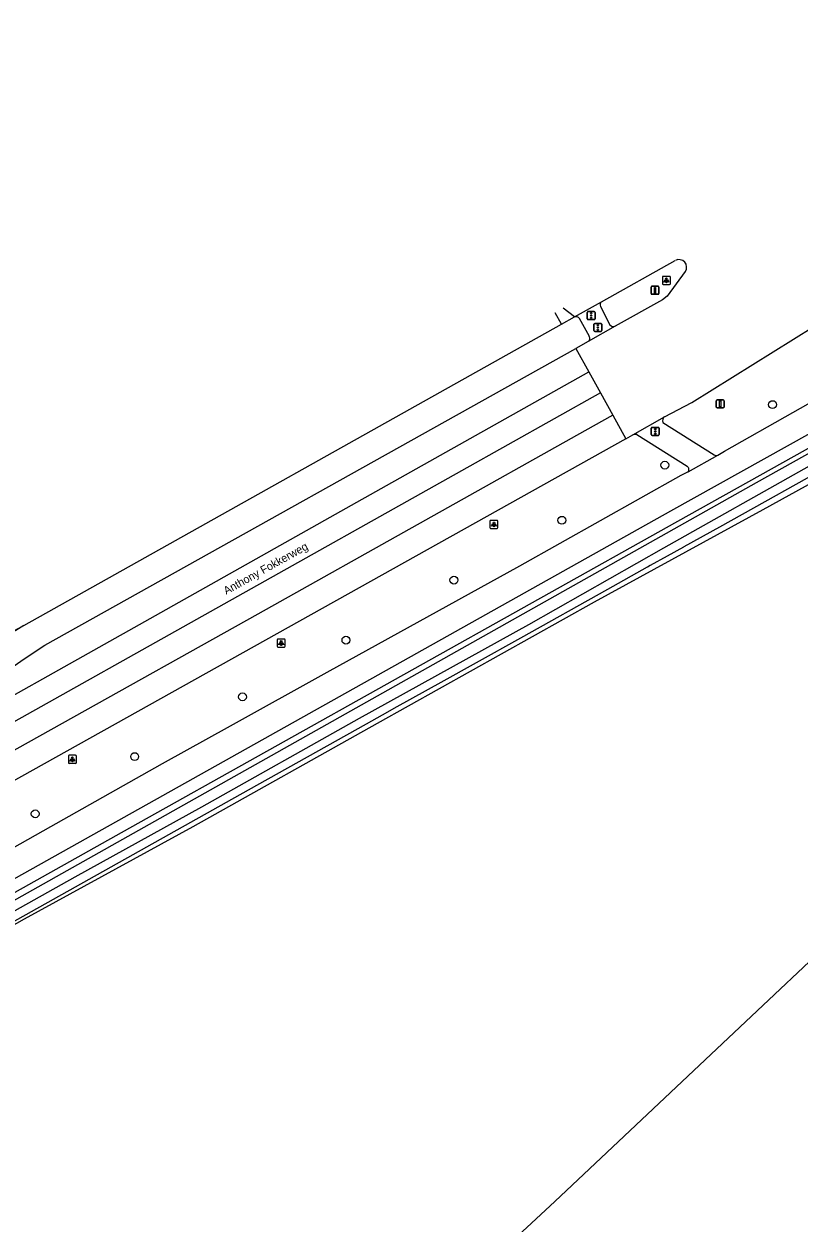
# Model space of a CAD drawing. Extents: x 157154 to 159278, y 385000 to 386650.
# Drawn here: x 157263.6 to 157360.5, y 386097.5 to 386247.3 of the extents above; entities that cross this region are included whole.
import ezdxf

# ---------------------------------------------------------------- set-up
doc = ezdxf.new("R2010")
doc.units = 0
for name, color, linetype in [('IMGEO_Boom', 7, 'Continuous'), ('IMGEO_Bouwland', 7, 'Continuous'), ('IMGEO_Fietspad_gesloten', 7, 'Continuous'), ('IMGEO_Fietspad_open', 7, 'Continuous'), ('IMGEO_Groenvoorziening', 7, 'Continuous'), ('IMGEO_Lichtpunt', 7, 'Continuous'), ('IMGEO_Loofbos', 7, 'Continuous'), ('IMGEO_Openbare_ruimte_label', 7, 'Continuous'), ('IMGEO_Portaal', 7, 'Continuous'), ('IMGEO_Rijbaan_regionaal_gesloten', 7, 'Continuous'), ('IMGEO_Verkeersregelinstallatiepaal', 7, 'Continuous'), ('IMGEO_Voetpad_open', 7, 'Continuous'), ('IMGEO_Waterloop', 7, 'Continuous')]:
    doc.layers.add(name, color=color, linetype=linetype)

msp = doc.modelspace()

# ---------------------------------------------------------------- linework, layer by layer
at = {"layer": 'IMGEO_Boom'}
for centre in [(157357.17, 386199.78), (157343.71, 386192.22), (157330.85, 386185.33), (157317.36, 386177.85), (157303.87, 386170.35), (157290.95, 386163.26), (157277.48, 386155.8), (157265.05, 386148.65)]:
    msp.add_circle(centre, 0.489, dxfattribs=at)
at = {"layer": 'IMGEO_Bouwland'}
msp.add_lwpolyline([(157390.33, 386206.23), (157370.97, 386194.93), (157355.94, 386186.64), (157334.87, 386175.09), (157307.76, 386159.95), (157284.74, 386147.04), (157263.69, 386135.49), (157241.46, 386122.96), (157215.19, 386108.12), (157203.72, 386101.65), (157202.61, 386100.97)], dxfattribs=at)
at = {"layer": 'IMGEO_Fietspad_gesloten'}
for points in [[(157350.32, 386193.47), (157351.18, 386193.97), (157376.79, 386208.46)], [(157379.77, 386206.17), (157344.43, 386186.45), (157276.11, 386148.18), (157237.43, 386126.52), (157197.41, 386104.01), (157185.77, 386096.92)], [(157346.62, 386191.38), (157350.32, 386193.47)], [(157346.62, 386191.38), (157345.73, 386190.93), (157325.57, 386179.6), (157301.5, 386166.32), (157289.42, 386159.61), (157280.92, 386154.89), (157265.99, 386146.48), (157249.02, 386136.91), (157232.77, 386127.85), (157216.57, 386118.79), (157199.15, 386108.93), (157192.54, 386105.06), (157189.59, 386103.18), (157183.83, 386099.48)]]:
    msp.add_lwpolyline(points, dxfattribs=at)
at = {"layer": 'IMGEO_Fietspad_open'}
for points in [[(157335.66, 386212.04), (157336.85, 386209.75)], [(157334.28, 386208.3), (157333.04, 386210.54)], [(157343.48, 386197.56), (157349.86, 386193.5)], [(157340.23, 386196.05), (157346.52, 386192.07)]]:
    msp.add_lwpolyline(points, dxfattribs=at)
for centre, radius, start, end in [((157336.15, 386212.23), 0.525, 133.694, 201.4184), ((157332.63, 386210.28), 0.484, 32.5209, 113.9937), ((157337.28, 386210.07), 0.535, 217.4867, 294.815), ((157333.86, 386208.07), 0.477, 303.1806, 29.0462), ((157344.03, 386197.79), 0.598, 129.3964, 202.7643), ((157340.1, 386195.09), 0.974, 82.0163, 112.7027), ((157350.12, 386193.89), 0.469, 236.3585, 295.7342), ((157346.25, 386191.68), 0.47, 321.1296, 55.9729)]:
    msp.add_arc(centre, radius, start, end, dxfattribs=at)
at = {"layer": 'IMGEO_Groenvoorziening'}
msp.add_lwpolyline([(157436.28, 386247.34), (157433.75, 386245.51), (157419, 386234.87), (157403.65, 386220.37), (157399.91, 386217.07), (157393.88, 386212.34), (157382.1, 386205.07), (157355.13, 386190.01), (157200.73, 386103.12)], dxfattribs=at)
at = {"layer": 'IMGEO_Lichtpunt'}
for p, q in [((157343.41, 386215.7), (157343.41, 386214.89)), ((157343.41, 386215.7), (157343.41, 386214.89)), ((157344.31, 386215.79), (157343.5, 386215.79)), ((157344.31, 386215.79), (157343.5, 386215.79)), ((157344.41, 386214.89), (157344.41, 386215.7)), ((157344.41, 386214.89), (157344.41, 386215.7)), ((157343.5, 386214.8), (157344.31, 386214.8)), ((157343.5, 386214.8), (157344.31, 386214.8)), ((157321.86, 386185.22), (157321.86, 386184.41)), ((157321.86, 386185.22), (157321.86, 386184.41)), ((157322.76, 386185.31), (157321.95, 386185.31)), ((157322.76, 386185.31), (157321.95, 386185.31)), ((157321.95, 386184.31), (157322.76, 386184.31)), ((157321.95, 386184.31), (157322.76, 386184.31)), ((157322.86, 386184.41), (157322.86, 386185.22)), ((157322.86, 386184.41), (157322.86, 386185.22)), ((157295.28, 386170.39), (157295.28, 386169.59)), ((157295.28, 386170.39), (157295.28, 386169.59)), ((157296.18, 386170.49), (157295.37, 386170.49)), ((157296.18, 386170.49), (157295.37, 386170.49)), ((157295.37, 386169.49), (157296.18, 386169.49)), ((157295.37, 386169.49), (157296.18, 386169.49)), ((157296.28, 386169.59), (157296.28, 386170.39)), ((157296.28, 386169.59), (157296.28, 386170.39)), ((157269.2, 386155.86), (157269.2, 386155.05)), ((157269.2, 386155.86), (157269.2, 386155.05)), ((157270.1, 386155.96), (157269.29, 386155.96)), ((157270.1, 386155.96), (157269.29, 386155.96)), ((157270.19, 386155.05), (157270.19, 386155.86)), ((157270.19, 386155.05), (157270.19, 386155.86)), ((157269.29, 386154.96), (157270.1, 386154.96)), ((157269.29, 386154.96), (157270.1, 386154.96))]:
    msp.add_line(p, q, dxfattribs=at)
for points in [[(157343.78, 386215.36), (157343.82, 386215.33), (157343.64, 386215.07), (157343.6, 386215.1), (157343.78, 386215.36)], [(157343.89, 386215.31), (157343.93, 386215.31), (157343.93, 386214.99), (157343.89, 386214.99), (157343.89, 386215.31)], [(157344, 386215.33), (157344.03, 386215.36), (157344.22, 386215.1), (157344.18, 386215.07), (157344, 386215.33)], [(157322.23, 386184.88), (157322.27, 386184.85), (157322.09, 386184.59), (157322.05, 386184.62), (157322.23, 386184.88)], [(157322.34, 386184.83), (157322.38, 386184.83), (157322.38, 386184.51), (157322.34, 386184.51), (157322.34, 386184.83)], [(157322.45, 386184.85), (157322.48, 386184.88), (157322.67, 386184.62), (157322.63, 386184.59), (157322.45, 386184.85)], [(157295.65, 386170.06), (157295.69, 386170.03), (157295.5, 386169.77), (157295.47, 386169.8), (157295.65, 386170.06)], [(157295.75, 386170.01), (157295.8, 386170.01), (157295.8, 386169.69), (157295.75, 386169.69), (157295.75, 386170.01)], [(157295.86, 386170.03), (157295.9, 386170.06), (157296.09, 386169.79), (157296.05, 386169.77), (157295.86, 386170.03)], [(157269.57, 386155.52), (157269.61, 386155.5), (157269.42, 386155.23), (157269.38, 386155.26), (157269.57, 386155.52)], [(157269.67, 386155.48), (157269.72, 386155.48), (157269.72, 386155.15), (157269.67, 386155.15), (157269.67, 386155.48)], [(157269.78, 386155.5), (157269.82, 386155.52), (157270.01, 386155.26), (157269.97, 386155.23), (157269.78, 386155.5)]]:
    msp.add_lwpolyline(points, dxfattribs=at)
for centre in [(157343.91, 386215.5), (157322.36, 386185.01), (157295.78, 386170.19), (157269.7, 386155.66)]:
    msp.add_circle(centre, 0.0994, dxfattribs=at)
for centre, start, end in [((157343.5, 386215.7), 90, 180), ((157343.5, 386215.7), 90, 180), ((157344.31, 386215.7), 0, 90), ((157344.31, 386215.7), 0, 90), ((157343.5, 386214.89), 180, 270), ((157343.5, 386214.89), 180, 270), ((157344.31, 386214.89), 270, 0), ((157344.31, 386214.89), 270, 360), ((157321.95, 386185.22), 90, 180), ((157321.95, 386185.22), 90, 180), ((157321.95, 386184.41), 180, 270), ((157321.95, 386184.41), 180, 270), ((157322.76, 386185.22), 0, 90), ((157322.76, 386185.22), 0, 90), ((157322.76, 386184.41), 270, 0), ((157322.76, 386184.41), 270, 360), ((157295.37, 386170.39), 90, 180), ((157295.37, 386170.39), 90, 180), ((157295.37, 386169.59), 180, 270), ((157295.37, 386169.59), 180, 270), ((157296.18, 386170.39), 0, 90), ((157296.18, 386170.39), 0, 90), ((157296.18, 386169.59), 270, 0), ((157296.18, 386169.59), 270, 360), ((157269.29, 386155.86), 90, 180), ((157269.29, 386155.86), 90, 180), ((157270.1, 386155.86), 0, 90), ((157270.1, 386155.86), 0, 90), ((157269.29, 386155.05), 180, 270), ((157269.29, 386155.05), 180, 270), ((157270.1, 386155.05), 270, 0), ((157270.1, 386155.05), 270, 360)]:
    msp.add_arc(centre, 0.0946, start, end, dxfattribs=at)
at = {"layer": 'IMGEO_Loofbos'}
msp.add_lwpolyline([(157269.71, 386044.28), (157329.95, 386100.2), (157465.79, 386228.19)], dxfattribs=at)
at = {"layer": 'IMGEO_Portaal'}
for p, q in [((157341.99, 386213.66), (157341.99, 386214.46)), ((157341.99, 386214.46), (157341.99, 386213.66)), ((157342.09, 386214.56), (157342.88, 386214.56)), ((157342.88, 386214.56), (157342.09, 386214.56)), ((157342.98, 386214.46), (157342.98, 386213.66)), ((157342.98, 386213.66), (157342.98, 386214.46)), ((157342.88, 386213.56), (157342.09, 386213.56)), ((157342.09, 386213.56), (157342.88, 386213.56)), ((157350.13, 386199.47), (157350.13, 386200.27)), ((157350.13, 386200.27), (157350.13, 386199.47)), ((157350.23, 386200.37), (157351.02, 386200.37)), ((157351.02, 386200.37), (157350.23, 386200.37)), ((157351.02, 386199.37), (157350.23, 386199.37)), ((157350.23, 386199.37), (157351.02, 386199.37)), ((157351.12, 386200.27), (157351.12, 386199.47)), ((157351.12, 386199.47), (157351.12, 386200.27))]:
    msp.add_line(p, q, dxfattribs=at)
for points in [[(157342.41, 386214.43), (157342.56, 386214.43), (157342.56, 386213.68), (157342.41, 386213.68), (157342.41, 386214.43)], [(157350.55, 386200.24), (157350.7, 386200.24), (157350.7, 386199.49), (157350.55, 386199.49), (157350.55, 386200.24)]]:
    msp.add_lwpolyline(points, dxfattribs=at)
for centre, start, end in [((157342.09, 386214.46), 90, 180), ((157342.09, 386214.46), 90, 180), ((157342.88, 386214.46), 0, 90), ((157342.88, 386214.46), 360, 90), ((157342.09, 386213.66), 180, 270), ((157342.09, 386213.66), 180, 270), ((157342.88, 386213.66), 270, 0), ((157342.88, 386213.66), 270, 0), ((157350.23, 386200.27), 90, 180), ((157350.23, 386200.27), 90, 180), ((157350.23, 386199.47), 180, 270), ((157350.23, 386199.47), 180, 270), ((157351.02, 386200.27), 0, 90), ((157351.02, 386200.27), 360, 90), ((157351.02, 386199.47), 270, 0), ((157351.02, 386199.47), 270, 0)]:
    msp.add_arc(centre, 0.1, start, end, dxfattribs=at)
at = {"layer": 'IMGEO_Rijbaan_regionaal_gesloten'}
for points in [[(157335.78, 386212.61), (157345.02, 386217.79)], [(157343.65, 386198.26), (157347.07, 386200.05), (157364.88, 386211.12), (157375.45, 386217.91)], [(157346.27, 386216.4), (157344.02, 386213.34), (157343.42, 386212.88), (157337.5, 386209.59)], [(157332.43, 386210.73), (157335.78, 386212.61)], [(157330.82, 386209.82), (157330.01, 386211.25)], [(157332.43, 386210.73), (157331.03, 386211.82)], [(157263.65, 386172.17), (157330.82, 386209.82)], [(157330.82, 386209.82), (157332.43, 386210.73)], [(157337.5, 386209.59), (157334.12, 386207.67)], [(157240.83, 386152.18), (157263.78, 386168.11), (157266.27, 386169.72), (157332.58, 386206.81)], [(157334.12, 386207.67), (157332.58, 386206.81)], [(157332.58, 386206.81), (157334.23, 386203.86)], [(157237.49, 386149.89), (157240.31, 386151.11), (157250.85, 386157.01), (157278.73, 386172.69), (157303.89, 386186.84), (157334.23, 386203.86)], [(157334.23, 386203.86), (157335.68, 386201.24)], [(157335.68, 386201.24), (157318.3, 386191.5), (157258.89, 386158.17), (157216.94, 386134.69), (157193.46, 386121.56), (157168.5, 386107.59), (157166.44, 386106.42)], [(157335.68, 386201.24), (157337.22, 386198.47)], [(157337.22, 386198.47), (157334.76, 386197.07), (157292.87, 386173.61), (157243.95, 386146.28), (157212.52, 386128.73), (157195.04, 386118.96), (157188.07, 386115.07), (157169.62, 386104.67)], [(157337.22, 386198.47), (157338.86, 386195.51)], [(157339.72, 386195.99), (157343.65, 386198.26)], [(157338.86, 386195.51), (157194.86, 386115.1), (157183.78, 386108.82)], [(157338.86, 386195.51), (157339.72, 386195.99)], [(157156.88, 386112.35), (157170.87, 386120.3), (157180.62, 386125.8), (157221.27, 386148.62), (157242.45, 386160.5), (157256.54, 386168.42), (157263.65, 386172.17)]]:
    msp.add_lwpolyline(points, dxfattribs=at)
for centre, radius, start, end in [((157345.48, 386216.94), 0.962, 325.8104, 118.0682), ((157293.25, 386121.6), 58.6, 120.3446, 126.416)]:
    msp.add_arc(centre, radius, start, end, dxfattribs=at)
at = {"layer": 'IMGEO_Verkeersregelinstallatiepaal'}
for p, q in [((157334.01, 386210.5), (157334.01, 386211.3)), ((157334.01, 386211.3), (157334.01, 386210.5)), ((157334.11, 386211.4), (157334.9, 386211.4)), ((157334.9, 386211.4), (157334.11, 386211.4)), ((157335, 386211.3), (157335, 386210.5)), ((157335, 386210.5), (157335, 386211.3)), ((157334.9, 386210.4), (157334.11, 386210.4)), ((157334.11, 386210.4), (157334.9, 386210.4)), ((157334.85, 386209.02), (157334.85, 386209.82)), ((157334.85, 386209.82), (157334.85, 386209.02)), ((157334.95, 386209.92), (157335.74, 386209.92)), ((157335.74, 386209.92), (157334.95, 386209.92)), ((157335.84, 386209.82), (157335.84, 386209.02)), ((157335.84, 386209.02), (157335.84, 386209.82)), ((157335.74, 386208.92), (157334.95, 386208.92)), ((157334.95, 386208.92), (157335.74, 386208.92)), ((157342.02, 386196.03), (157342.02, 386196.83)), ((157342.02, 386196.83), (157342.02, 386196.03)), ((157342.12, 386196.93), (157342.91, 386196.93)), ((157342.91, 386196.93), (157342.12, 386196.93)), ((157343.01, 386196.83), (157343.01, 386196.03)), ((157343.01, 386196.03), (157343.01, 386196.83)), ((157342.91, 386195.93), (157342.12, 386195.93)), ((157342.12, 386195.93), (157342.91, 386195.93))]:
    msp.add_line(p, q, dxfattribs=at)
for centre in [(157334.51, 386211.19), (157334.51, 386210.9), (157334.51, 386210.61), (157335.34, 386209.71), (157335.34, 386209.42), (157335.34, 386209.13), (157342.51, 386196.72), (157342.51, 386196.43), (157342.51, 386196.14)]:
    msp.add_circle(centre, 0.085, dxfattribs=at)
for centre, start, end in [((157334.11, 386211.3), 90, 180), ((157334.11, 386211.3), 90, 180), ((157334.9, 386211.3), 0, 90), ((157334.9, 386211.3), 360, 90), ((157334.11, 386210.5), 180, 270), ((157334.11, 386210.5), 180, 270), ((157334.95, 386209.82), 90, 180), ((157334.95, 386209.82), 90, 180), ((157334.9, 386210.5), 270, 0), ((157334.9, 386210.5), 270, 0), ((157335.74, 386209.82), 0, 90), ((157335.74, 386209.82), 360, 90), ((157334.95, 386209.02), 180, 270), ((157334.95, 386209.02), 180, 270), ((157335.74, 386209.02), 270, 0), ((157335.74, 386209.02), 270, 0), ((157342.12, 386196.83), 90, 180), ((157342.12, 386196.83), 90, 180), ((157342.12, 386196.03), 180, 270), ((157342.12, 386196.03), 180, 270), ((157342.91, 386196.83), 0, 90), ((157342.91, 386196.83), 360, 90), ((157342.91, 386196.03), 270, 0), ((157342.91, 386196.03), 270, 0)]:
    msp.add_arc(centre, 0.1, start, end, dxfattribs=at)
at = {"layer": 'IMGEO_Voetpad_open'}
msp.add_lwpolyline([(157199.17, 386103.32), (157238.29, 386125.27), (157276.87, 386146.91), (157345.32, 386185.22), (157380.46, 386204.84)], dxfattribs=at)
at = {"layer": 'IMGEO_Waterloop'}
for points in [[(157201.18, 386101.43), (157202.96, 386102.52), (157212.1, 386107.78), (157227.68, 386116.76), (157241.55, 386124.52), (157251.2, 386130.23), (157270.05, 386140.77), (157285.86, 386149.52), (157305.57, 386160.6), (157326.74, 386172.3), (157343.57, 386181.89), (157361.8, 386192.13), (157380.17, 386202.19), (157390.14, 386207.76)], [(157365.75, 386192.98), (157350.53, 386184.48), (157346.08, 386182), (157346.04, 386181.98), (157343.99, 386180.83), (157341.88, 386179.66), (157341.53, 386179.46), (157341.51, 386179.45), (157336.56, 386176.68), (157325.68, 386170.61), (157320.14, 386167.52), (157315.72, 386165.05), (157310.25, 386162), (157308.4, 386160.97), (157306.41, 386159.86), (157291.66, 386151.62), (157240.15, 386122.76), (157227.09, 386115.36), (157223.24, 386113.18), (157223.23, 386113.17), (157222.82, 386112.94), (157206.44, 386103.66), (157201.54, 386100.81)]]:
    msp.add_lwpolyline(points, dxfattribs=at)

# ---------------------------------------------------------------- texts
at = {"layer": 'IMGEO_Openbare_ruimte_label'}
msp.add_text('Anthony Fokkerweg', height=1, rotation=29.2048, dxfattribs=at).set_placement((157288.92, 386176))

doc.saveas('drawing.dxf')
